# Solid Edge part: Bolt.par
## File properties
Author: Sarvanan
Template: Sync Iso Part.par
Last saved by: CADCIM
Revision: 8
Application: Solid Edge
Accuracy: 0.990
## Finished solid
Body 1: solid body, 12 faces, 22 edges, 12 vertices.
  Faces by surface: plane 7, spun 4, cylinder 1
  Edges by curve: line 8, circle 7, intersection 7
Bounding box of the edges (mm; curved faces can reach further): 24.000 x 24.000 x 104.000, from (0, -2.3071, 0) to (24, 21.6929, 104).
Cylindrical faces by radius (mm): R6 x1
Planar faces by outward normal: +x 1, +y 1, +z 2, -x 1, -y 1, -z 1
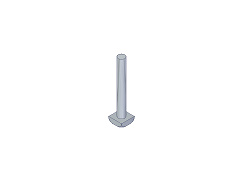
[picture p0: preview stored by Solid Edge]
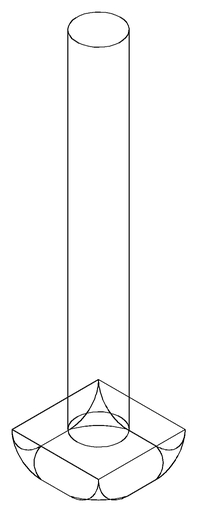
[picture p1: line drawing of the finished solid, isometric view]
